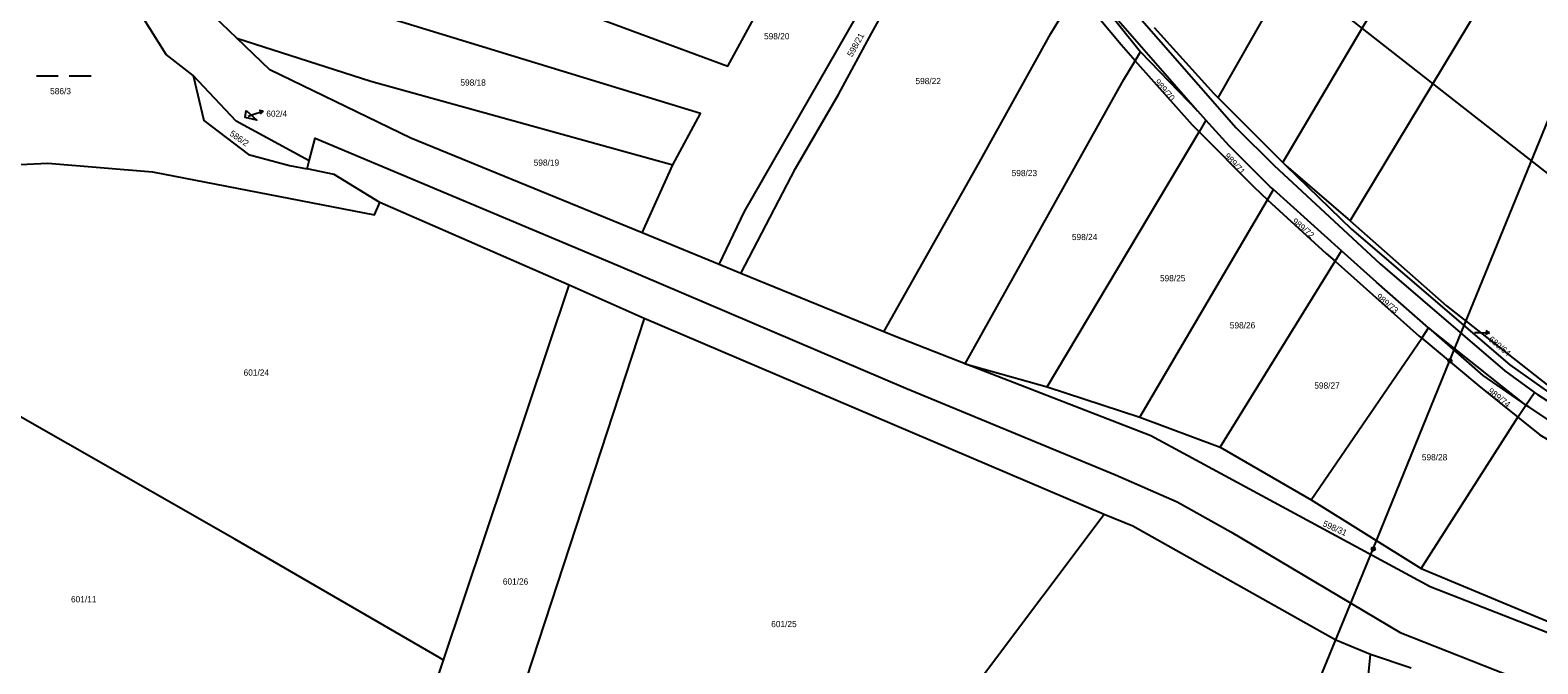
# Model space of a CAD drawing. Extents: x -757266 to -753360, y -1162585 to -1157740.
# Drawn here: x -756524.8 to -756112.6, y -1160912.3 to -1160739.1 of the extents above; entities that cross this region are included whole.
import ezdxf

# ---------------------------------------------------------------- set-up
doc = ezdxf.new("R2010")
doc.units = 0
for name, color, linetype in [('Hranice parcel', 7, 'Continuous'), ('Parcelní čísla', 7, 'Continuous'), ('Pop  PČ popisy', 7, 'Continuous'), ('Poz předměty', 7, 'Continuous'), ('Vnitřní kresba', 7, 'Continuous'), ('Značky kultur', 7, 'Continuous')]:
    doc.layers.add(name, color=color, linetype=linetype)

msp = doc.modelspace()

# ---------------------------------------------------------------- linework, layer by layer
at = {"layer": 'Hranice parcel'}
for p, q in [((-756236.84, -1160725.41), (-756221.16, -1160745.04)), ((-756222.64, -1160747.45), (-756221.16, -1160745.04)), ((-756221.16, -1160745.04), (-756205.63, -1160761.14)), ((-756199.96, -1160757.57), (-756182.28, -1160775.25)), ((-756205.63, -1160761.14), (-756203.3, -1160763.71)), ((-756203.3, -1160763.71), (-756205.2, -1160766.91)), ((-756246.72, -1160836.57), (-756205.2, -1160766.91)), ((-756449.07, -1160777.03), (-756448.49, -1160774.8)), ((-756357.44, -1160794.53), (-756349.1, -1160775.9)), ((-756182.28, -1160775.25), (-756181.48, -1160776.05)), ((-756181.48, -1160776.05), (-756163.89, -1160791.22)), ((-756186.43, -1160785.44), (-756184.81, -1160782.69)), ((-756166.23, -1160799.4), (-756184.81, -1160782.69)), ((-756377.4, -1160808.8), (-756429.23, -1160786.23)), ((-756221.4, -1160844.94), (-756186.43, -1160785.44)), ((-756336.44, -1160803.13), (-756357.44, -1160794.53)), ((-756167.99, -1160802.25), (-756166.23, -1160799.4)), ((-756330.46, -1160805.58), (-756336.44, -1160803.13)), ((-756291.38, -1160821.59), (-756330.46, -1160805.58)), ((-756199.43, -1160853.11), (-756167.99, -1160802.25)), ((-756411.75, -1160911.32), (-756377.4, -1160808.8)), ((-756356.87, -1160817.89), (-756377.4, -1160808.8)), ((-756356.87, -1160817.89), (-756391.53, -1160923.69)), ((-756231.14, -1160871.55), (-756356.87, -1160817.89)), ((-756144.32, -1160823.31), (-756142.42, -1160820.52)), ((-756115.8, -1160841.6), (-756142.42, -1160820.52)), ((-756174.52, -1160867.55), (-756144.32, -1160823.31)), ((-756269.14, -1160830.3), (-756246.72, -1160836.57)), ((-756246.72, -1160836.57), (-756221.4, -1160844.94)), ((-756115.8, -1160841.6), (-756113.47, -1160838.15)), ((-756118.01, -1160844.88), (-756115.8, -1160841.6)), ((-756221.4, -1160844.94), (-756199.43, -1160853.11)), ((-756144.48, -1160886.24), (-756118.01, -1160844.88)), ((-756199.43, -1160853.11), (-756174.52, -1160867.55)), ((-756174.52, -1160867.55), (-756144.48, -1160886.24)), ((-756144.48, -1160886.24), (-756095.27, -1160906.86)), ((-756147.22, -1160913.56), (-756158.32, -1160909.77))]:
    msp.add_line(p, q, dxfattribs=at)
for points in [[(-756199.96, -1160757.57), (-756148.77, -1160667.64), (-756129.07, -1160631.4), (-756085.47, -1160554.79), (-756057.12, -1160502.92)], [(-756182.28, -1160775.25), (-756081.45, -1160604.56), (-756034.61, -1160517.94)], [(-756163.89, -1160791.22), (-756080.08, -1160652.29), (-756042.01, -1160586.57), (-756012.75, -1160533.8)], [(-756336.44, -1160803.13), (-756329.46, -1160788.64), (-756296.36, -1160731.1), (-756273.64, -1160688.29)], [(-756330.46, -1160805.58), (-756315.56, -1160776.94), (-756303.77, -1160756.7), (-756294.62, -1160739.81), (-756269.02, -1160693.57)], [(-756488.17, -1160696.58), (-756454.55, -1160708.4), (-756382.34, -1160731.11), (-756334.05, -1160748.92), (-756326.92, -1160735.86)], [(-756480.23, -1160751.48), (-756487.64, -1160745.78), (-756504.99, -1160717.9)], [(-756468.31, -1160741.24), (-756474.57, -1160735.24), (-756485.28, -1160716.9)], [(-756349.1, -1160775.9), (-756341.49, -1160761.89), (-756430.96, -1160734.5), (-756485.28, -1160716.9)], [(-756291.38, -1160821.59), (-756265.25, -1160775.21), (-756245.73, -1160740.02), (-756238.7, -1160728.46)], [(-756222.64, -1160747.45), (-756226.49, -1160743.1), (-756238.7, -1160728.46)], [(-756217.45, -1160738.36), (-756201.13, -1160756.4), (-756199.96, -1160757.57)], [(-756357.44, -1160794.53), (-756420.7, -1160768.62), (-756459.28, -1160749.89), (-756468.31, -1160741.24)], [(-756468.31, -1160741.24), (-756431.63, -1160753), (-756349.1, -1160775.9)], [(-756269.14, -1160830.3), (-756225.79, -1160752.56), (-756222.64, -1160747.45)], [(-756205.2, -1160766.91), (-756207.02, -1160765.08), (-756222.64, -1160747.45)], [(-756448.49, -1160774.8), (-756468.47, -1160763.94), (-756480.23, -1160751.48)], [(-756480.23, -1160751.48), (-756477.3, -1160763.77), (-756465.1, -1160773.04), (-756453.89, -1160776.07), (-756449.07, -1160777.03)], [(-756465.74, -1160761.08), (-756462.82, -1160763.71), (-756465.97, -1160762.93), (-756465.74, -1160761.08)], [(-756184.81, -1160782.69), (-756185.71, -1160781.88), (-756196.92, -1160770.74), (-756203.3, -1160763.71)], [(-756448.49, -1160774.8), (-756446.87, -1160768.63), (-756364.04, -1160803.45), (-756285.34, -1160837.01), (-756228.03, -1160860.65), (-756211.13, -1160868.06), (-756196.47, -1160876.25), (-756150.21, -1160903.76), (-756104.93, -1160921.67)], [(-756205.2, -1160766.91), (-756190.24, -1160781.96), (-756186.43, -1160785.44)], [(-756564.85, -1160779.26), (-756550.37, -1160776.94), (-756519.98, -1160775.43), (-756491.36, -1160777.85), (-756430.66, -1160789.59), (-756429.23, -1160786.23)], [(-756429.23, -1160786.23), (-756441.65, -1160778.52), (-756449.07, -1160777.03)], [(-756181.48, -1160776.05), (-756163.48, -1160793.52), (-756120.18, -1160830.61), (-756102.71, -1160843.03), (-756079.79, -1160857.04), (-756062.93, -1160866.47), (-756042.41, -1160877.1), (-756023.28, -1160887.48)], [(-756186.43, -1160785.44), (-756170.4, -1160800.11), (-756167.99, -1160802.25)], [(-756163.89, -1160791.22), (-756137.53, -1160814.5), (-756107.48, -1160838.11)], [(-756142.42, -1160820.52), (-756156.67, -1160807.99), (-756166.23, -1160799.4)], [(-756167.99, -1160802.25), (-756145.03, -1160822.71), (-756144.32, -1160823.31)], [(-756411.75, -1160911.32), (-756412.97, -1160910.58), (-756468.87, -1160878.23), (-756514.46, -1160852.21), (-756582.55, -1160813.38)], [(-756269.14, -1160830.3), (-756288.43, -1160822.8), (-756291.38, -1160821.59)], [(-756144.32, -1160823.31), (-756128.72, -1160836.3), (-756118.01, -1160844.88)], [(-756063.22, -1160919.58), (-756083.48, -1160914.18), (-756141.99, -1160891.33), (-756218.41, -1160850.03), (-756269.14, -1160830.3)], [(-756113.47, -1160838.15), (-756112.69, -1160838.72), (-756087.18, -1160855.04), (-756052.12, -1160874.24), (-756024.11, -1160889.41), (-756013.76, -1160895.68)], [(-756072.45, -1160867.77), (-756097.55, -1160853.7), (-756114.97, -1160842.17), (-756115.8, -1160841.6)], [(-756118.01, -1160844.88), (-756112.01, -1160849.69), (-756094.09, -1160860.33), (-756074.46, -1160871.21)], [(-756231.14, -1160871.55), (-756264.65, -1160916.19), (-756280.54, -1160941.57), (-756284.06, -1160946.51)], [(-756158.32, -1160909.77), (-756167.75, -1160905.9), (-756223.29, -1160874.75), (-756231.14, -1160871.55)], [(-756391.53, -1160923.69), (-756405.26, -1160963.49), (-756426.28, -1160954.74), (-756411.75, -1160911.32)], [(-756108.4, -1161121.99), (-756143.44, -1161091.07), (-756148.04, -1161082.81), (-756173.25, -1161060.58), (-756158.32, -1160909.77)]]:
    msp.add_lwpolyline(points, dxfattribs=at)
at = {"layer": 'Pop  PČ popisy'}
for p, q in [((-756465.2, -1160762.57), (-756463.96, -1160762.17)), ((-756463.96, -1160762.17), (-756461.106, -1160761.243)), ((-756461.106, -1160761.243), (-756462.213, -1160761.076)), ((-756461.106, -1160761.243), (-756461.904, -1160762.028)), ((-756129.83, -1160821.72), (-756128.81, -1160821.76)), ((-756128.81, -1160821.76), (-756125.811, -1160821.865)), ((-756125.811, -1160821.865), (-756126.829, -1160822.33)), ((-756125.811, -1160821.865), (-756126.794, -1160821.329))]:
    msp.add_line(p, q, dxfattribs=at)
at = {"layer": 'Poz předměty'}
for p, q in [((-756106.41, -1160780.95), (-756289.5, -1160637.61)), ((-756136.61, -1160829.45), (-756095.13, -1160727.9)), ((-756157.54, -1160880.91), (-756136.61, -1160829.45)), ((-756176.5, -1160926.92), (-756157.54, -1160880.91))]:
    msp.add_line(p, q, dxfattribs=at)
for centre, radius in [((-756136.6134, -1160829.4499), 0.5), ((-756136.6134, -1160829.4499), 0.4), ((-756136.6134, -1160829.4499), 0.3), ((-756136.6134, -1160829.4499), 0.2), ((-756136.6134, -1160829.4499), 0.1), ((-756157.5434, -1160880.9099), 0.5), ((-756157.5434, -1160880.9099), 0.4), ((-756157.5434, -1160880.9099), 0.3), ((-756157.5434, -1160880.9099), 0.2), ((-756157.5434, -1160880.9099), 0.1)]:
    msp.add_circle(centre, radius, dxfattribs=at)
at = {"layer": 'Vnitřní kresba'}
for p, q in [((-756284.67, -1160663.34), (-756195.05, -1160765.75)), ((-756236.84, -1160725.41), (-756205.63, -1160761.14)), ((-756195.05, -1160765.75), (-756184.68, -1160776.12)), ((-756184.68, -1160776.12), (-756155.63, -1160803)), ((-756155.63, -1160803), (-756121.61, -1160832.19)), ((-756142.42, -1160820.52), (-756127.63, -1160833.53)), ((-756127.63, -1160833.53), (-756115.8, -1160841.6)), ((-756121.61, -1160832.19), (-756113.47, -1160838.15))]:
    msp.add_line(p, q, dxfattribs=at)
at = {"layer": 'Značky kultur'}
for p, q in [((-756523.109, -1160751.56), (-756517.109, -1160751.56)), ((-756514.109, -1160751.56), (-756508.109, -1160751.56))]:
    msp.add_line(p, q, dxfattribs=at)

# ---------------------------------------------------------------- texts
at = {"layer": 'Parcelní čísla'}
for s, p in [('598/20', (-756324.14, -1160741.6)), ('598/22', (-756282.73, -1160753.84)), ('586/3', (-756519.34, -1160756.6)), ('598/18', (-756407.16, -1160754.26)), ('602/4', (-756460.23, -1160762.768)), ('598/19', (-756387.12, -1160776.16)), ('598/23', (-756256.43, -1160779)), ('598/24', (-756239.96, -1160796.49)), ('598/25', (-756215.87, -1160807.77)), ('598/26', (-756196.78, -1160820.64)), ('601/24', (-756466.44, -1160833.55)), ('598/27', (-756173.67, -1160837.1)), ('598/28', (-756144.27, -1160856.72)), ('601/26', (-756395.56, -1160890.69)), ('601/11', (-756513.63, -1160895.54)), ('601/25', (-756322.17, -1160902.32))]:
    msp.add_text(s, height=1.7, dxfattribs=at).set_placement(p)
for s, rotation, p in [('598/21', 61, (-756300.036, -1160746.552)), ('989/70', 311, (-756217.481, -1160753.367)), ('586/2', 325, (-756470.447, -1160767.726)), ('989/71', 313, (-756198.401, -1160773.659)), ('989/72', 320, (-756179.906, -1160791.621)), ('989/73', 320, (-756156.916, -1160812.221)), ('680/64', 320, (-756126.191, -1160823.902)), ('989/74', 321.999997, (-756126.363, -1160838.089)), ('598/31', 336, (-756171.555, -1160874.616))]:
    msp.add_text(s, height=1.7, rotation=rotation, dxfattribs=at).set_placement(p)

doc.saveas('drawing.dxf')
